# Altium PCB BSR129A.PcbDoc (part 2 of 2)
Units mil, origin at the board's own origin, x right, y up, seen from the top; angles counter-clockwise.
Board outline 2165.87 x 2165.5 mil, 2 copper layers (Top Layer, Bottom Layer), stack 61.2 mil thick; 64 components, 16 nets, 93 pads, 184 vias.
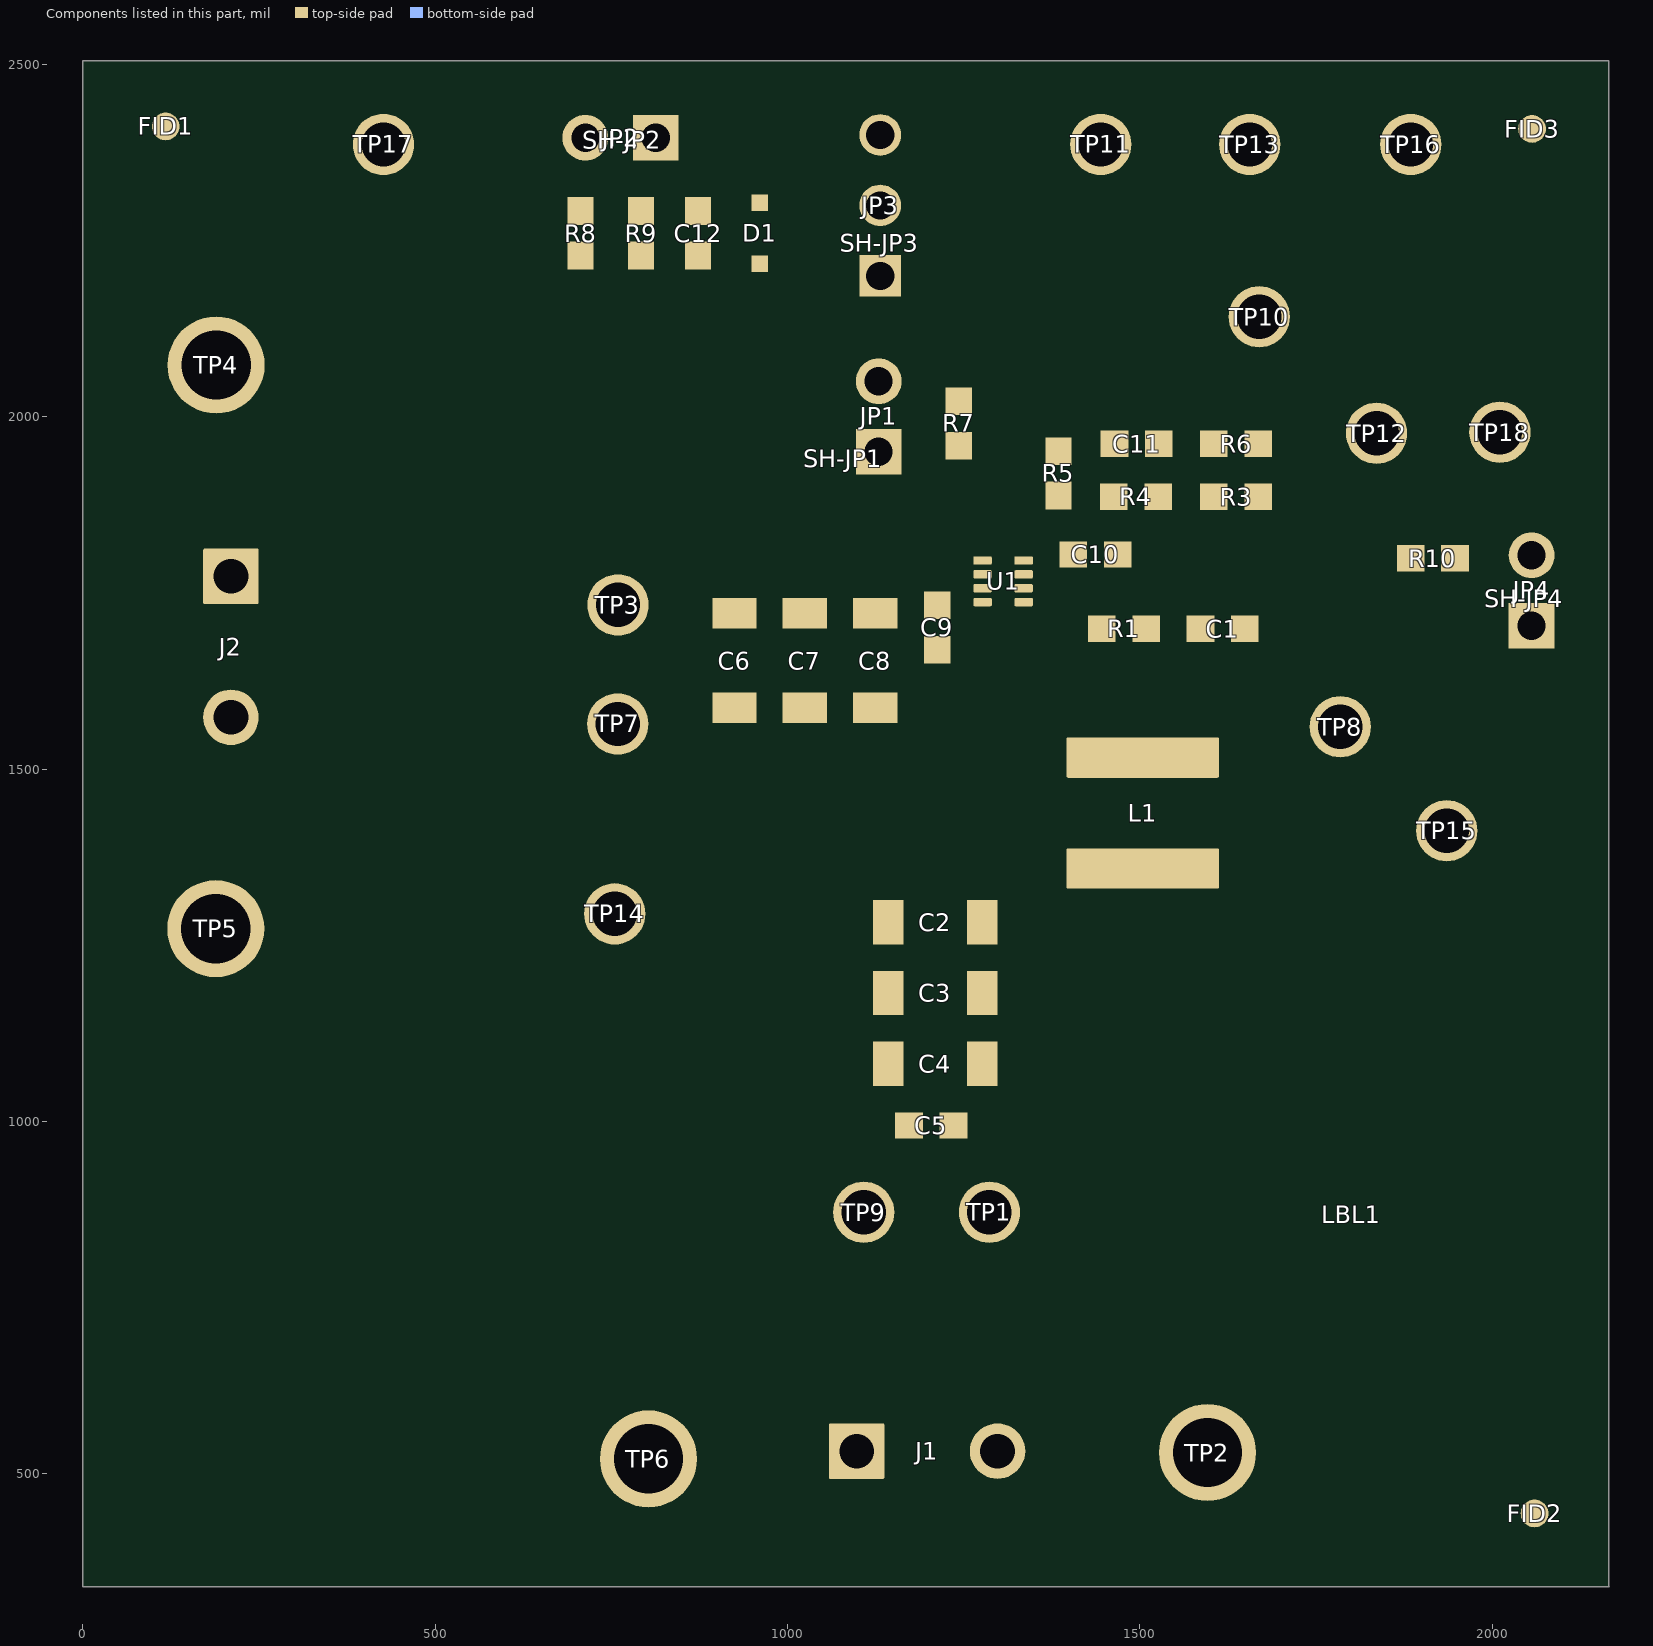
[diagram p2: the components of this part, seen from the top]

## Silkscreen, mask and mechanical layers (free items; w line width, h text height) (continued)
Drill Drawing:
  lines w10: 4081.59,1552.88 4136.84,1552.88 4136.84,1608.13 4081.59,1608.13 4081.59,1552.88 ; 4081.59,1691.01 4095.4,1691.01 4109.22,1677.2 4123.03,1691.01 4136.84,1691.01 4123.03,1704.82 4136.84,1718.64 4123.03,1718.64 4109.22,1732.45 4095.4,1718.64 4081.59,1718.64 4095.4,1704.82 4081.59,1691.01 ; 4081.59,1801.52 4109.22,1815.33 4136.84,1801.52 4123.03,1829.14 4136.84,1856.77 4109.22,1842.96 4081.59,1856.77 4095.4,1829.14 4081.59,1801.52 ; 4081.59,1981.09 4136.84,1981.09 4109.22,1925.84 4081.59,1981.09 ; 4081.59,2077.78 4109.22,2050.16 4136.84,2077.78 4109.22,2105.41 4081.59,2077.78
  lines w12: 4031.5,1515.58 7262.99,1515.58 ; 4031.5,2137.18 7262.99,2137.18 ; 4369.36,1391.26 4369.36,2261.5 ; 4701.36,1391.26 4701.36,2261.5 ; 5337.93,1391.26 5337.93,2261.5 ; 5597.07,1391.26 5597.07,2261.5 ; 5972.22,1391.26 5972.22,2261.5 ; 6696.55,1391.26 6696.55,2261.5 ; 4031.5,1391.26 7262.99,1391.26 7262.99,2261.5 4031.5,2261.5 4031.5,1391.26
  text "Symbol" at 4106.09,2174.48 h72
  text "Quantity" at 4406.66,2174.48 h72
  text "Finished Hole Size" at 4738.66,2174.48 h72
  text "Plated" at 5375.22,2174.48 h72
  text "Hole Type" at 5634.36,2174.48 h72
  text "Drill Layer Pair" at 6009.52,2174.48 h72
  text "Hole Tolerance" at 6733.85,2174.48 h72
  text "184" at 4406.66,2050.16 h60
  text "10.00mil (0.254mm)" at 4738.66,2050.16 h60
  text "PTH" at 5375.22,2050.16 h60
  text "Round" at 5634.36,2050.16 h60
  text "Top Layer - Bottom Layer" at 6009.52,2050.16 h60
  text "9" at 4406.66,1925.84 h60
  text "40.00mil (1.016mm)" at 4738.66,1925.84 h60
  text "PTH" at 5375.22,1925.84 h60
  text "Round" at 5634.36,1925.84 h60
  text "Top Layer - Bottom Layer" at 6009.52,1925.84 h60
  text "4" at 4406.66,1801.52 h60
  text "49.21mil (1.250mm)" at 4738.66,1801.52 h60
  text "PTH" at 5375.22,1801.52 h60
  text "Round" at 5634.36,1801.52 h60
  text "Top Layer - Bottom Layer" at 6009.52,1801.52 h60
  text "14" at 4406.66,1677.2 h60
  text "63.00mil (1.600mm)" at 4738.66,1677.2 h60
  text "PTH" at 5375.22,1677.2 h60
  text "Round" at 5634.36,1677.2 h60
  text "Top Layer - Bottom Layer" at 6009.52,1677.2 h60
  text "4" at 4406.66,1552.88 h60
  text "98.43mil (2.500mm)" at 4738.66,1552.88 h60
  text "PTH" at 5375.22,1552.88 h60
  text "Round" at 5634.36,1552.88 h60
  text "Top Layer - Bottom Layer" at 6009.52,1552.88 h60
  text "215 Total" at 4406.66,1428.56 h60
  text ".Layer_Name" at 570,-868.49 h60
M17 Embedded Cavity:
  text ".Layer_Name" at 570,-868.49 h60
M18 Embedded Assembly:
  text ".Layer_Name" at 570,-868.49 h60
M19 Embedded Keepout:
  text ".Layer_Name" at 570,-868.49 h60

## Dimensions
0.65,2504.37 to 0.65,339.02 on M2 Board Dimensions
1.15,340.15 to 2166.5,340.15 on M2 Board Dimensions
-7,-410 to 993,-410 on M2 Board Dimensions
